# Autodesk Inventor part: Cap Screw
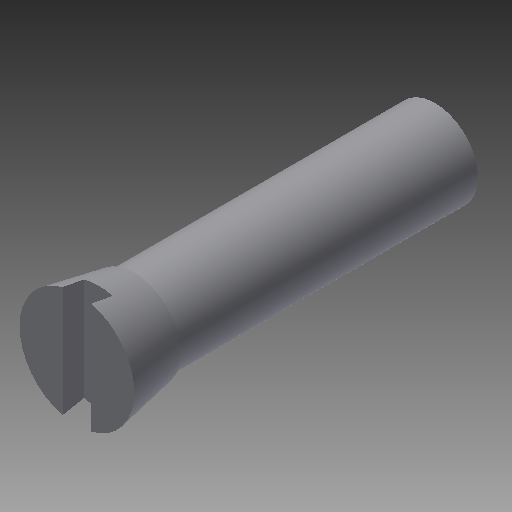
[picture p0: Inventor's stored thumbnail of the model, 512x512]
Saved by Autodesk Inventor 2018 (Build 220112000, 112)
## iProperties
Shininess: 77.0
Length Units: 11269
Angle Units: 11279
Time Units: 11290
Mass Units: 11283
Length Display Precision: 3
Angle Display Precision: 2
Created: 2002-02
Part Number: Cap Screw
Document SubType Name: Modeling
Designer: ***
Density: 1 g/cm^3
Material: Generic
Appearance: Default
Density: 0.0
Volumn: 0.0
Area: 0.0
PropertySet Name: Model Information
Control State: 0
Master: False
Checked Out: False
Author: ***
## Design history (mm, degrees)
sketch "Sketch1"
  geometry: L1 (0, 27.83)-(4, 27.83); L2 (4, 27.83)-(3.25, 23.83); L3 (3.25, 23.83)-(0, 23.83); L4 (0, 23.83)-(0, 27.83)
  constraints: 8 end point, 1 horizontal, 1 parallel, 1 perpendicular, 1 point on line
  dimensions: "d2" = 4 distance from line of L1 L2.end; "d5" = 8 diameter of L1.end L4; "d6" = 6.5 diameter of L3.start L4; "d14" = 4 distance of L3.end L1.start
revolve "Revolution1" sketch "Sketch1" stored, may be unused: angle "d7" = 90 deg
sketch "Sketch2"
  geometry: C1 r 3 at (0, 0)
  constraints: 1 centre point
  dimensions: "d8" = 6 diameter of C1
extrude "Extrusion1" join sketch "Sketch2" distance "d9" = 21; taper "d10" = 0 deg
sketch "Sketch3"
  geometry: L1 (-1, 28.967)-(1, 28.967); L2 (1, 28.967)-(1, 26.33); L3 (1, 26.33)-(-1, 26.33); L4 (-1, 26.33)-(-1, 28.967); L5 (-4, 27.83)-(4, 27.83) reference
  constraints: 8 end point, 2 parallel, 1 horizontal, 1 perpendicular
  dimensions: "d11" = 2 distance of L1.start L1.end; "d15" = 1.5 distance between parallel lines of L5 L3
extrude "Extrusion2" cut sketch "Sketch3" extent not by distance; stored distance "d12" = 24; taper "d13" = 0 deg
body "Solid1"
